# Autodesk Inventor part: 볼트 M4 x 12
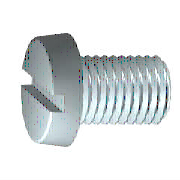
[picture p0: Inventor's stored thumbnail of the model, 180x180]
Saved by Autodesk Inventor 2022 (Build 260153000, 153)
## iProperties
Created: 2012-02
Part Number: 볼트 M4 x 12
Material: 강철, 연강
Description: 6각머리 태핑 나사
Document SubType Name: Modeling
Standard: KS B 1021
Designer: mduedu
Standards Organization: KS
Language: ko-KR
Size Designation: A  M 4 x 12
Categories: <MemberInstance><Categories><Category DisplayName="조임쇠" InternalName="e4da775c-781d-43d5-af7c-5136215cf5a6" Mnemonic="FSTN"><Category DisplayName="볼트" InternalN
Density: 1 g/cm^3
Appearance: 강철
IsCustomPart: 0
Author: mduedu
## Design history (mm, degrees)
body "Solid1"
revolve "본체" stored, may be unused: angle "d8" = 90 deg
sketch "스케치2"
  geometry: L1 (0, 0)-(0, 3.273) reference; L2 (-3.5, 0.6)-(3.5, 0.6); L3 (3.5, 0.6)-(3.5, -0.6); L4 (3.5, -0.6)-(-3.5, -0.6); L5 (-3.5, -0.6)-(-3.5, 0.6); L6 (-3.5, 0)-(3.5, 0); L7 (0, 0.6)-(0, -0.6); C1 r 3.5 at (0, 0) reference; 1 further point
  constraints: 12 end point, 5 midpoint, 2 parallel, 1 collinear, 1 horizontal, 1 perpendicular
  dimensions: "d11" = 1.2 distance of L4.end L2.start (= SBR); "d12" = 7 distance of L2.start L2.end (= KOD)
fillet "모깎기1" dims "d14" = 0.2 (= RR)
extrude "슬롯" cut sketch "스케치2" distance "d19" = 1.1 (= STI); taper "d20" = 0 deg
feature "스레드" dims "d15" = 10.6 (= GEL), "d16" = 0
chamfer "모따기1" distance "d17" = 0.42941 (= -0.5 x SPD + 0.5 x GD); stored, may be unused: second distance "d18" = 0.42952 (computed from GUL), angle "d36" = 45 deg
workplane "Work Plane1"
sketch "스케치1"
  geometry: L1 (-2.6, 0)-(12, 0); L2 (12, 0)-(12, 2); L3 (12, 2)-(1.4, 2); L4 (1.4, 2)-(0.97, 1.785); L5 (0.97, 1.785)-(0, 1.785); L6 (0, 1.785)-(0, 3.5); L7 (-5.52, 0)-(14.92, 0) reference; L8 (0, -0.7)-(0, 4.2) reference; L9 (-2.6, 0)-(-2.6, 3.273); L10 (0, 3.5)-(-2.6, 3.273); L11 (1.4, 2)-(0, 2)
  constraints: 18 end point, 4 parallel, 2 collinear, 2 perpendicular, 1 horizontal, 1 point on line
  dimensions: "d0" = 12 distance between parallel lines of L2 L6 (= NLG); "d1" = 10.6 distance from line of L3.end L2 (= GEL); "d2" = 0.42952 horizontal distance of L4.end L3.end (computed from GAL); "d3" = 2.6 distance from line of L1.start L6 (= KOH); "d4" = 4 diameter of L3 L1 (= GD); "d5" = 3.5705 diameter of L5 L1 (= BDM); "d9" = 7 diameter of L6.end L1 (= KOD); "d10" = 5 deg angle of L10 L1 (= KEWI)
other parameters: "GD" = 4 (= NND) [user parameter; used in 2 equation terms], "NLG" = 12 [user parameter; used in 1 equation term], "GEL" = 10.6 [user parameter; used in 2 equation terms], "KOD" = 7 [user parameter; used in 2 equation terms], "KOH" = 2.6 [user parameter; used in 1 equation term], "GAL" = 0.42941 (= 0.61345 x PTC) [user parameter; used in 1 equation term], "SPD" = 3.14117 (= NND - 1.2269 x PTC) [user parameter; used in 1 equation term], "BDM" = 3.5705 [user parameter; used in 1 equation term], "GUL" = 0.42941 (= 0.61345 x PTC) [user parameter; used in 1 equation term], "RR" = 0.2 [user parameter; used in 1 equation term], "d7" = 0, "SBR" = 1.2 [user parameter; used in 1 equation term], "STI" = 1.1 [user parameter; used in 1 equation term], "KEWI" = 5 deg [user parameter; used in 1 equation term], "d37" = 0, "d39" = 0, "PTC" = 0.7 [user parameter; used in 5 equation terms], "THREADDIA" = 4 [user parameter; used in 1 equation term], "TOA" = 30 deg [user parameter], "TPU" = 14.28571 (computed from PTC) [user parameter], "NND" = 4 [user parameter; used in 2 equation terms], "GD1" = 3.14117 (= THREADDIA - 1.2269 x PTC) [user parameter]
